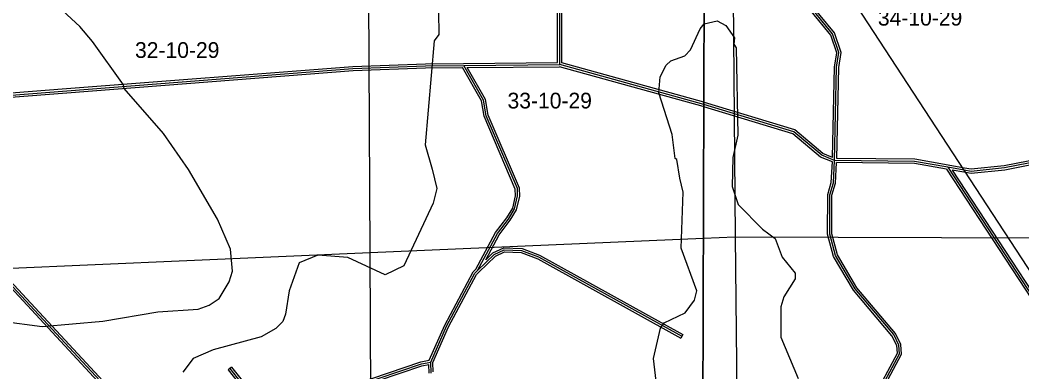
# Model space of a CAD drawing. Extents: x 457167 to 656239, y 1787309 to 1969297.
# Drawn here: x 527283 to 541585, y 1906256 to 1911287 of the extents above; entities that cross this region are included whole.
import ezdxf

# ---------------------------------------------------------------- set-up
doc = ezdxf.new("R2010")
doc.units = 0
for name, color, linetype in [('Level 1', 7, 'Continuous'), ('Level 2', 7, 'Continuous'), ('Level 31', 7, 'Continuous'), ('Level 32', 7, 'Continuous'), ('Level 55', 7, 'Continuous'), ('Level 63', 7, 'Continuous'), ('Level 7', 7, 'Continuous')]:
    doc.layers.add(name, color=color, linetype=linetype)

msp = doc.modelspace()

# ---------------------------------------------------------------- linework, layer by layer
at = {"layer": 'Level 1'}
for p, q in [((537449.415, 1913450.626), (537491.16, 1908193.626)), ((532281.084, 1907962.091), (532250.887, 1913167.832)), ((532281.084, 1907962.091), (537038.261, 1908170.188)), ((537038.261, 1908170.188), (537485.081, 1908189.733)), ((537485.081, 1908189.733), (542774.254, 1908171.988)), ((537491.16, 1908193.626), (537546.665, 1902924.331)), ((527049.27, 1907733.409), (532281.084, 1907962.091)), ((532306.15, 1902834.307), (532281.084, 1907962.091))]:
    msp.add_line(p, q, dxfattribs=at)
at = {"layer": 'Level 31'}
for p, q in [((534986.798, 1910649.551), (534984.26, 1916478.475)), ((533615.535, 1910636.612), (534986.798, 1910649.551)), ((540760.35, 1909140.507), (540524.94, 1909182.335)), ((540524.94, 1909182.335), (545795.278, 1901112.589)), ((534193.3, 1908001.531), (534443.12, 1907992.346)), ((533783.107, 1900354.301), (527053.695, 1907611.555)), ((533152.758, 1906238.376), (533145.019, 1906396.589))]:
    msp.add_line(p, q, dxfattribs=at)
for points in [[(538909.852, 1909277.964), (538938.548, 1910611.731), (538972.581, 1910819.993), (538881.566, 1911086.835), (538474.405, 1911588.142), (538424.664, 1911738.486), (538287.69, 1912942.232)], [(524844.744, 1910033.591), (527949.486, 1910275.801), (532035.339, 1910593.878), (533069.445, 1910631.879), (533615.535, 1910636.612)], [(533812.14, 1907704.962), (534096.473, 1908232.766), (534255.14, 1908440.251), (534343.353, 1908586.51), (534384.965, 1908771.106), (534382.133, 1908876.573), (533938.013, 1909919.161), (533900.606, 1910142.199), (533615.535, 1910636.612)], [(537044.395, 1910079.199), (537044.335, 1910079.217), (534986.798, 1910649.551)], [(545407.038, 1910460.895), (545264.995, 1910261.315), (544713.161, 1909720.776), (544295.368, 1909363.481), (544103.396, 1909264.058), (543870.035, 1909248.037), (543670.277, 1909306.828), (543495.389, 1909390.634), (543037.149, 1909533.491), (542386.64, 1909376.935), (541335.465, 1909171.447), (540860.421, 1909122.741), (540760.35, 1909140.507)], [(538909.852, 1909277.964), (538726.683, 1909353.456), (538327.555, 1909687.825), (537044.395, 1910079.199)], [(539403.889, 1900723.442), (539267.811, 1902841.381), (539243.303, 1902933.097), (539219.447, 1903433.186), (539153.87, 1903808.675), (538955.089, 1904284.226), (538955.825, 1904617.687), (539006.131, 1904742.621), (539040.143, 1904942.521), (539140.832, 1905217.482), (539836.34, 1906516.053), (539828.149, 1906641.173), (539753.599, 1906791.23), (539205.078, 1907443.159), (538923.034, 1907918.973), (538840.41, 1908227.608), (538841.86, 1908786.165), (538892.32, 1908961.283), (538909.852, 1909277.964)], [(540524.94, 1909182.335), (540051.903, 1909266.363), (538909.852, 1909277.964)], [(533812.14, 1907704.962), (534051.309, 1907935.452), (534193.3, 1908001.531)], [(534443.12, 1907992.346), (534684.72, 1907899.912), (536731.058, 1906766.675)], [(533145.019, 1906396.589), (533372.112, 1906912.577), (533775.15, 1907669.811), (533812.14, 1907704.962)], [(530277.025, 1906307.319), (530434.654, 1906106.777), (530609.585, 1906039.272), (532085.312, 1906058.661), (533011.74, 1906371.94), (533145.019, 1906396.589)]]:
    msp.add_lwpolyline(points, dxfattribs=at)
at = {"layer": 'Level 32'}
for p, q in [((534956.786, 1910679.27), (534954.26, 1916478.461)), ((535016.789, 1910672.371), (535014.26, 1916478.488)), ((533615.251, 1910666.611), (534956.785, 1910679.27)), ((533667.184, 1910607.096), (534982.856, 1910619.511)), ((537044.495, 1910110.305), (535016.789, 1910672.369)), ((540506.919, 1909155.066), (545742.53, 1901138.489)), ((540765.598, 1909170.045), (540530.19, 1909211.872)), ((540755.101, 1909110.969), (540587.99, 1909140.661)), ((540587.99, 1909140.661), (545810.647, 1901143.92)), ((534187.188, 1908031.776), (534449.195, 1908022.142)), ((534199.413, 1907971.285), (534437.046, 1907962.547)), ((533743.569, 1900352.818), (527031.697, 1907591.156)), ((533779.608, 1900402.198), (527075.695, 1907631.953)), ((536745.592, 1906792.92), (536716.524, 1906740.43)), ((530300.612, 1906325.858), (530253.438, 1906288.78)), ((533122.769, 1906237.425), (533116.731, 1906360.846)), ((533181.952, 1906255.637), (533175.33, 1906390.982))]:
    msp.add_line(p, q, dxfattribs=at)
for points in [[(538880.801, 1909322.385), (538908.6, 1910614.486), (538941.761, 1910817.417), (538854.901, 1911072.079), (538447.651, 1911573.497), (538395.206, 1911732.011), (538257.882, 1912938.841)], [(538940.499, 1909307.654), (538968.495, 1910608.975), (539003.4, 1910822.568), (538908.232, 1911101.591), (538501.16, 1911602.786), (538454.121, 1911744.963), (538317.498, 1912945.625)], [(524842.411, 1910063.501), (527947.155, 1910305.711), (532033.624, 1910623.836), (533068.764, 1910661.875), (533615.274, 1910666.612)], [(524874.689, 1910005.836), (527951.818, 1910245.891), (532037.055, 1910563.921), (533070.127, 1910601.884), (533598.29, 1910606.461)], [(533788, 1907723.408), (534071.192, 1908249.096), (534230.304, 1908457.161), (534315.155, 1908597.846), (534354.875, 1908774.047), (534352.297, 1908870.065), (533909.015, 1909910.682), (533871.915, 1910131.901), (533598.29, 1910606.461)], [(533929.69, 1907859.91), (534121.754, 1908216.437), (534279.975, 1908423.339), (534371.551, 1908575.174), (534415.055, 1908768.164), (534411.97, 1908883.081), (533967.011, 1909927.638), (533929.299, 1910152.497), (533667.184, 1910607.096)], [(537044.295, 1910047.865), (537035.951, 1910050.41), (534982.856, 1910619.511)], [(545408.334, 1910410.976), (545287.892, 1910241.748), (544733.43, 1909698.634), (544312.237, 1909338.431), (544111.663, 1909234.554), (543866.725, 1909217.739), (543659.49, 1909278.73), (543484.385, 1909362.64), (543036.121, 1909502.386), (542393.03, 1909347.616), (541339.881, 1909141.742), (540859.308, 1909092.468), (540755.105, 1909110.968)], [(545369.628, 1910460.068), (545242.099, 1910280.882), (544692.893, 1909742.916), (544278.499, 1909388.529), (544095.129, 1909293.562), (543873.345, 1909278.336), (543681.063, 1909334.926), (543506.393, 1909418.628), (543038.175, 1909564.596), (542380.25, 1909406.254), (541331.047, 1909201.152), (540861.535, 1909153.013), (540765.593, 1909170.046)], [(538878.72, 1909258.346), (538710.968, 1909327.483), (538312.967, 1909660.909), (537044.295, 1910047.865)], [(538880.801, 1909322.386), (538742.398, 1909379.428), (538342.144, 1909714.741), (537052.72, 1910108.025), (537044.495, 1910110.305)], [(540530.188, 1909211.873), (540054.697, 1909296.337), (538940.5, 1909307.654)], [(539371.222, 1900763.987), (539238.063, 1902836.5), (539213.49, 1902928.457), (539189.57, 1903429.877), (539124.895, 1903800.204), (538925.075, 1904278.24), (538925.838, 1904623.533), (538977.097, 1904750.835), (539011.028, 1904950.258), (539113.388, 1905229.784), (539805.843, 1906522.655), (539798.605, 1906633.211), (539728.33, 1906774.664), (539180.53, 1907425.735), (538895.121, 1907907.227), (538810.399, 1908223.7), (538811.87, 1908790.439), (538862.552, 1908966.329), (538878.72, 1909258.346)], [(539431.58, 1900760.361), (539297.56, 1902846.262), (539273.115, 1902937.736), (539249.324, 1903436.493), (539182.845, 1903817.146), (538985.103, 1904290.212), (538985.813, 1904611.841), (539035.165, 1904734.409), (539069.258, 1904934.782), (539168.276, 1905205.181), (539866.836, 1906509.452), (539857.693, 1906649.135), (539778.867, 1906807.796), (539229.625, 1907460.583), (538950.946, 1907930.72), (538870.42, 1908231.516), (538871.85, 1908781.89), (538922.087, 1908956.236), (538938.222, 1909247.672)], [(540506.919, 1909155.065), (540049.108, 1909236.389), (538938.222, 1909247.672)], [(533929.69, 1907859.91), (534034.103, 1907960.536), (534187.188, 1908031.776)], [(534449.195, 1908022.143), (534697.41, 1907927.179), (536745.592, 1906792.92)], [(533832.958, 1907683.361), (534068.515, 1907910.37), (534199.413, 1907971.285)], [(534437.046, 1907962.546), (534672.032, 1907872.646), (536716.524, 1906740.43)], [(533123.955, 1906423.201), (533345.104, 1906925.686), (533750.954, 1907688.205), (533788.001, 1907723.408)], [(533175.33, 1906390.982), (533399.12, 1906899.469), (533799.345, 1907651.417), (533832.806, 1907683.215)], [(530300.612, 1906325.858), (530453.145, 1906131.798), (530614.982, 1906069.346), (532080.185, 1906088.596), (533004.169, 1906401.049), (533123.955, 1906423.201)], [(530253.438, 1906288.78), (530416.162, 1906081.756), (530604.188, 1906009.198), (532090.439, 1906028.725), (533019.313, 1906342.831), (533116.731, 1906360.846)]]:
    msp.add_lwpolyline(points, dxfattribs=at)
at = {"layer": 'Level 55'}
for p, q in [((540760.35, 1909140.507), (538287.69, 1912942.232)), ((545974.317, 1901126.966), (540760.35, 1909140.507))]:
    msp.add_line(p, q, dxfattribs=at)
at = {"layer": 'Level 63'}
for points in [[(497176.54, 1878534.741), (536942.563, 1878385.707), (537088.612, 1923840.983), (497371.386, 1923990.389), (497176.54, 1878534.741)], [(536942.563, 1878385.707), (576708.29, 1878279.4), (576805.546, 1923734.416), (537088.612, 1923840.983), (536942.563, 1878385.707)]]:
    msp.add_lwpolyline(points, dxfattribs=at)
at = {"layer": 'Level 7'}
for points in [[(527022.6, 1906980.55), (527597.573, 1906903.696), (528464.819, 1906984.279), (529248.851, 1907115.141), (529824.192, 1907154.96), (529982.774, 1907212.823), (530124.785, 1907304.067), (530267.294, 1907545.365), (530317.763, 1907695.249), (530285.437, 1908012.136), (530103.406, 1908437.874), (529688.876, 1909147.806), (529332.08, 1909665.803), (528767.269, 1910309.531), (528759.088, 1910359.552), (528319.229, 1910977.881), (528136.541, 1911195.214), (527521.45, 1911764.049)], [(533255.729, 1911403.854), (533263.025, 1911078.706), (533196.045, 1910987.233)], [(537048.103, 1911233.128), (537048.236, 1911233.299), (537231.77, 1911274.392), (537356.623, 1911207.282), (537481.108, 1911031.83), (537472.48, 1910940.157), (537505.661, 1910890.046), (537526.651, 1909639.487), (537458.945, 1909322.939), (537449.272, 1908906.149), (537531.787, 1908647.464), (537880.8, 1908296.19), (538063.775, 1908162.219), (538162.962, 1907895.134), (538345.649, 1907669.461), (538345.35, 1907586.099), (538186.141, 1907328.191), (538144.003, 1907186.607), (538142.63, 1906753.116), (538390.794, 1906160.446)], [(536721.172, 1908024.819), (536748.76, 1908825.048), (536699.365, 1909025.252), (536658.56, 1909292.178), (536633.59, 1909308.908), (536593.013, 1909650.836), (536403.18, 1910243.337), (536420.596, 1910476.693), (536504.485, 1910643.158), (536571.375, 1910701.28), (536771.668, 1910775.684), (536855.299, 1910858.787), (536989.656, 1911158.436), (537048.103, 1911233.128)], [(533196.045, 1910987.233), (533066.256, 1909503.756), (533165.154, 1909153.33), (533230.96, 1908878.004), (533180.292, 1908669.759), (532760.569, 1907770.772), (532493.415, 1907646.576), (531960.671, 1907890.065), (531535.622, 1907924.75), (531268.529, 1907817.224), (531125.503, 1907417.543), (531074.447, 1907084.244), (531032.409, 1906976.001), (530932.038, 1906876.297), (530723.276, 1906760.272), (530039.076, 1906570.729), (529755.252, 1906446.602), (529604.573, 1906255.356)], [(536373.017, 1906041.877), (536324.3, 1906450.526), (536425.745, 1906883.688), (536475.994, 1906958.551), (536776.558, 1907099.287), (536910.527, 1907282.263), (536944.296, 1907415.547), (536721.172, 1908024.819)]]:
    msp.add_lwpolyline(points, dxfattribs=at)

# ---------------------------------------------------------------- texts
at = {"layer": 'Level 2'}
for s, p in [('34-10-29', (539528.195, 1911206.437)), ('32-10-29', (528924.372, 1910744.781)), ('33-10-29', (534241.64, 1910022.333))]:
    msp.add_text(s, height=225, dxfattribs=at).set_placement(p)

doc.saveas('drawing.dxf')
